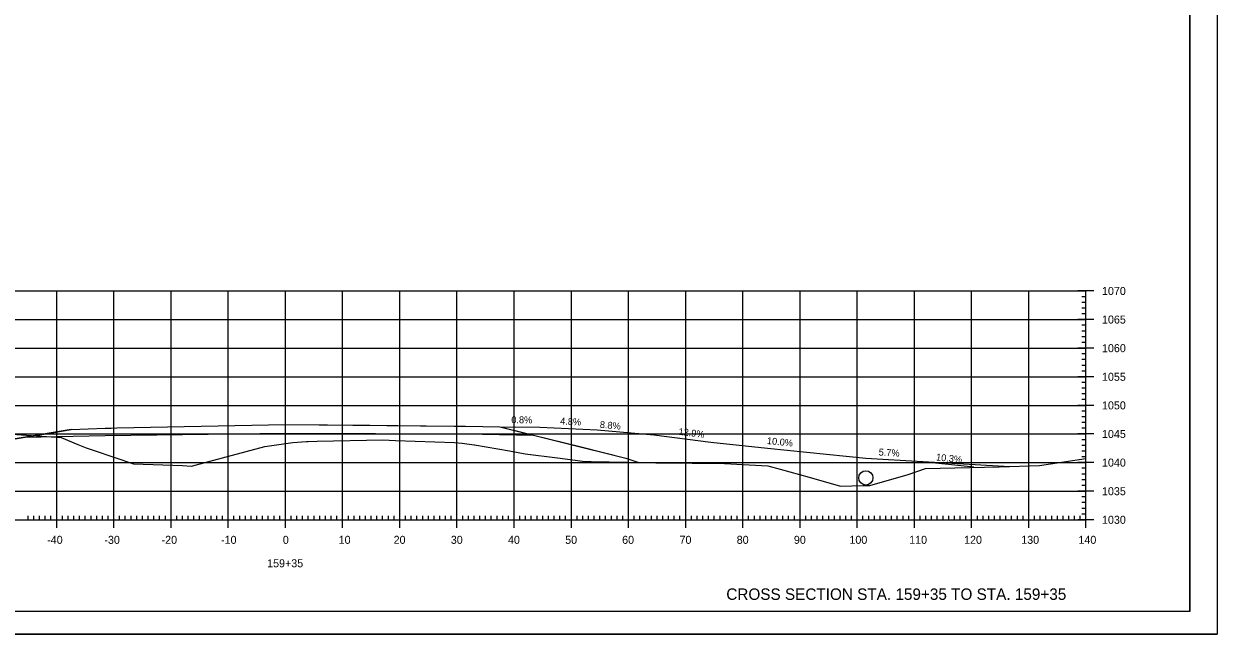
# Model space of a CAD drawing. Extents: x 1322838 to 1324533, y 339903 to 351025.
# Drawn here: x 1324107.5 to 1324316.2, y 345572 to 345678.7 of the extents above; entities that cross this region are included whole.
import ezdxf

# ---------------------------------------------------------------- set-up
doc = ezdxf.new("R2010")
doc.units = 0
for name, color, linetype in [('R_Alt Surface', 7, 'Continuous'), ('R_Axis', 7, 'Continuous'), ('R_Axis Annot', 7, 'Continuous'), ('R_Border', 7, 'Continuous'), ('R_Draft', 7, 'Continuous'), ('R_Drive', 7, 'Continuous'), ('R_Exist Surface', 7, 'Continuous'), ('R_Fin Surface', 7, 'Continuous'), ('R_Grid', 7, 'Continuous'), ('R_MOT', 7, 'Continuous'), ('R_No Plot', 7, 'Continuous'), ('R_Water', 7, 'Continuous')]:
    doc.layers.add(name, color=color, linetype=linetype)

msp = doc.modelspace()

# ---------------------------------------------------------------- linework, layer by layer
at = {"layer": 'R_Alt Surface'}
for points in [[(1324115.74, 345607.74), (1324093.74, 345604.08), (1324073.62, 345610.78)], [(1324107.75, 345606.41), (1324121.74, 345606.69), (1324153.24, 345607.11), (1324184.74, 345607.01), (1324196.63, 345606.78)], [(1324190.74, 345608.25), (1324212.74, 345602.75), (1324214.87, 345602.04)]]:
    msp.add_lwpolyline(points, dxfattribs=at)
at = {"layer": 'R_Axis'}
for p, q in [((1324294.64, 345631.97), (1324291.84, 345631.97)), ((1324293.24, 345591.97), (1324293.24, 345631.97)), ((1324293.24, 345630.97), (1324292.54, 345630.97)), ((1324293.24, 345629.97), (1324292.54, 345629.97)), ((1324293.24, 345628.97), (1324292.54, 345628.97)), ((1324293.24, 345627.97), (1324292.54, 345627.97)), ((1324294.64, 345626.97), (1324291.84, 345626.97)), ((1324293.24, 345625.97), (1324292.54, 345625.97)), ((1324293.24, 345624.97), (1324292.54, 345624.97)), ((1324293.24, 345623.97), (1324292.54, 345623.97)), ((1324293.24, 345622.97), (1324292.54, 345622.97)), ((1324294.64, 345621.97), (1324291.84, 345621.97)), ((1324293.24, 345620.97), (1324292.54, 345620.97)), ((1324293.24, 345619.97), (1324292.54, 345619.97)), ((1324293.24, 345618.97), (1324292.54, 345618.97)), ((1324294.64, 345616.97), (1324291.84, 345616.97)), ((1324293.24, 345617.97), (1324292.54, 345617.97)), ((1324293.24, 345615.97), (1324292.54, 345615.97)), ((1324293.24, 345614.97), (1324292.54, 345614.97)), ((1324293.24, 345613.97), (1324292.54, 345613.97)), ((1324293.24, 345612.97), (1324292.54, 345612.97)), ((1324294.64, 345611.97), (1324291.84, 345611.97)), ((1324293.24, 345610.97), (1324292.54, 345610.97)), ((1324293.24, 345609.97), (1324292.54, 345609.97)), ((1324293.24, 345608.97), (1324292.54, 345608.97)), ((1324294.64, 345606.97), (1324291.84, 345606.97)), ((1324293.24, 345607.97), (1324292.54, 345607.97)), ((1324293.24, 345605.97), (1324292.54, 345605.97)), ((1324293.24, 345604.97), (1324292.54, 345604.97)), ((1324293.24, 345603.97), (1324292.54, 345603.97)), ((1324293.24, 345602.97), (1324292.54, 345602.97)), ((1324294.64, 345601.97), (1324291.84, 345601.97)), ((1324293.24, 345600.97), (1324292.54, 345600.97)), ((1324293.24, 345599.97), (1324292.54, 345599.97)), ((1324293.24, 345598.97), (1324292.54, 345598.97)), ((1324293.24, 345597.97), (1324292.54, 345597.97)), ((1324294.64, 345596.97), (1324291.84, 345596.97)), ((1324293.24, 345595.97), (1324292.54, 345595.97)), ((1324293.24, 345594.97), (1324292.54, 345594.97)), ((1324293.24, 345593.97), (1324292.54, 345593.97)), ((1324013.24, 345591.97), (1324293.24, 345591.97)), ((1324108.24, 345591.97), (1324108.24, 345592.67)), ((1324109.24, 345591.97), (1324109.24, 345592.67)), ((1324110.24, 345591.97), (1324110.24, 345592.67)), ((1324111.24, 345591.97), (1324111.24, 345592.67)), ((1324112.24, 345591.97), (1324112.24, 345592.67)), ((1324113.24, 345590.57), (1324113.24, 345593.37)), ((1324114.24, 345591.97), (1324114.24, 345592.67)), ((1324115.24, 345591.97), (1324115.24, 345592.67)), ((1324116.24, 345591.97), (1324116.24, 345592.67)), ((1324117.24, 345591.97), (1324117.24, 345592.67)), ((1324118.24, 345591.97), (1324118.24, 345592.67)), ((1324119.24, 345591.97), (1324119.24, 345592.67)), ((1324120.24, 345591.97), (1324120.24, 345592.67)), ((1324121.24, 345591.97), (1324121.24, 345592.67)), ((1324122.24, 345591.97), (1324122.24, 345592.67)), ((1324123.24, 345590.57), (1324123.24, 345593.37)), ((1324124.24, 345591.97), (1324124.24, 345592.67)), ((1324125.24, 345591.97), (1324125.24, 345592.67)), ((1324126.24, 345591.97), (1324126.24, 345592.67)), ((1324127.24, 345591.97), (1324127.24, 345592.67)), ((1324128.24, 345591.97), (1324128.24, 345592.67)), ((1324129.24, 345591.97), (1324129.24, 345592.67)), ((1324130.24, 345591.97), (1324130.24, 345592.67)), ((1324131.24, 345591.97), (1324131.24, 345592.67)), ((1324132.24, 345591.97), (1324132.24, 345592.67)), ((1324133.24, 345590.57), (1324133.24, 345593.37)), ((1324134.24, 345591.97), (1324134.24, 345592.67)), ((1324135.24, 345591.97), (1324135.24, 345592.67)), ((1324136.24, 345591.97), (1324136.24, 345592.67)), ((1324137.24, 345591.97), (1324137.24, 345592.67)), ((1324138.24, 345591.97), (1324138.24, 345592.67)), ((1324139.24, 345591.97), (1324139.24, 345592.67)), ((1324140.24, 345591.97), (1324140.24, 345592.67)), ((1324141.24, 345591.97), (1324141.24, 345592.67)), ((1324142.24, 345591.97), (1324142.24, 345592.67)), ((1324143.24, 345590.57), (1324143.24, 345593.37)), ((1324144.24, 345591.97), (1324144.24, 345592.67)), ((1324145.24, 345591.97), (1324145.24, 345592.67)), ((1324146.24, 345591.97), (1324146.24, 345592.67)), ((1324147.24, 345591.97), (1324147.24, 345592.67)), ((1324148.24, 345591.97), (1324148.24, 345592.67)), ((1324149.24, 345591.97), (1324149.24, 345592.67)), ((1324150.24, 345591.97), (1324150.24, 345592.67)), ((1324151.24, 345591.97), (1324151.24, 345592.67)), ((1324152.24, 345591.97), (1324152.24, 345592.67)), ((1324153.24, 345590.57), (1324153.24, 345593.37)), ((1324154.24, 345591.97), (1324154.24, 345592.67)), ((1324155.24, 345591.97), (1324155.24, 345592.67)), ((1324156.24, 345591.97), (1324156.24, 345592.67)), ((1324157.24, 345591.97), (1324157.24, 345592.67)), ((1324158.24, 345591.97), (1324158.24, 345592.67)), ((1324159.24, 345591.97), (1324159.24, 345592.67)), ((1324160.24, 345591.97), (1324160.24, 345592.67)), ((1324161.24, 345591.97), (1324161.24, 345592.67)), ((1324162.24, 345591.97), (1324162.24, 345592.67)), ((1324163.24, 345590.57), (1324163.24, 345593.37)), ((1324164.24, 345591.97), (1324164.24, 345592.67)), ((1324165.24, 345591.97), (1324165.24, 345592.67)), ((1324166.24, 345591.97), (1324166.24, 345592.67)), ((1324167.24, 345591.97), (1324167.24, 345592.67)), ((1324168.24, 345591.97), (1324168.24, 345592.67)), ((1324169.24, 345591.97), (1324169.24, 345592.67)), ((1324170.24, 345591.97), (1324170.24, 345592.67)), ((1324171.24, 345591.97), (1324171.24, 345592.67)), ((1324172.24, 345591.97), (1324172.24, 345592.67)), ((1324173.24, 345590.57), (1324173.24, 345593.37)), ((1324174.24, 345591.97), (1324174.24, 345592.67)), ((1324175.24, 345591.97), (1324175.24, 345592.67)), ((1324176.24, 345591.97), (1324176.24, 345592.67)), ((1324177.24, 345591.97), (1324177.24, 345592.67)), ((1324178.24, 345591.97), (1324178.24, 345592.67)), ((1324179.24, 345591.97), (1324179.24, 345592.67)), ((1324180.24, 345591.97), (1324180.24, 345592.67)), ((1324181.24, 345591.97), (1324181.24, 345592.67)), ((1324182.24, 345591.97), (1324182.24, 345592.67)), ((1324183.24, 345590.57), (1324183.24, 345593.37)), ((1324184.24, 345591.97), (1324184.24, 345592.67)), ((1324185.24, 345591.97), (1324185.24, 345592.67)), ((1324186.24, 345591.97), (1324186.24, 345592.67)), ((1324187.24, 345591.97), (1324187.24, 345592.67)), ((1324188.24, 345591.97), (1324188.24, 345592.67)), ((1324189.24, 345591.97), (1324189.24, 345592.67)), ((1324190.24, 345591.97), (1324190.24, 345592.67)), ((1324191.24, 345591.97), (1324191.24, 345592.67)), ((1324192.24, 345591.97), (1324192.24, 345592.67)), ((1324193.24, 345590.57), (1324193.24, 345593.37)), ((1324194.24, 345591.97), (1324194.24, 345592.67)), ((1324195.24, 345591.97), (1324195.24, 345592.67)), ((1324196.24, 345591.97), (1324196.24, 345592.67)), ((1324197.24, 345591.97), (1324197.24, 345592.67)), ((1324198.24, 345591.97), (1324198.24, 345592.67)), ((1324199.24, 345591.97), (1324199.24, 345592.67)), ((1324200.24, 345591.97), (1324200.24, 345592.67)), ((1324201.24, 345591.97), (1324201.24, 345592.67)), ((1324202.24, 345591.97), (1324202.24, 345592.67)), ((1324203.24, 345590.57), (1324203.24, 345593.37)), ((1324204.24, 345591.97), (1324204.24, 345592.67)), ((1324205.24, 345591.97), (1324205.24, 345592.67)), ((1324206.24, 345591.97), (1324206.24, 345592.67)), ((1324207.24, 345591.97), (1324207.24, 345592.67)), ((1324208.24, 345591.97), (1324208.24, 345592.67)), ((1324209.24, 345591.97), (1324209.24, 345592.67)), ((1324210.24, 345591.97), (1324210.24, 345592.67)), ((1324211.24, 345591.97), (1324211.24, 345592.67)), ((1324212.24, 345591.97), (1324212.24, 345592.67)), ((1324213.24, 345590.57), (1324213.24, 345593.37)), ((1324214.24, 345591.97), (1324214.24, 345592.67)), ((1324215.24, 345591.97), (1324215.24, 345592.67)), ((1324216.24, 345591.97), (1324216.24, 345592.67)), ((1324217.24, 345591.97), (1324217.24, 345592.67)), ((1324218.24, 345591.97), (1324218.24, 345592.67)), ((1324219.24, 345591.97), (1324219.24, 345592.67)), ((1324220.24, 345591.97), (1324220.24, 345592.67)), ((1324221.24, 345591.97), (1324221.24, 345592.67)), ((1324222.24, 345591.97), (1324222.24, 345592.67)), ((1324223.24, 345590.57), (1324223.24, 345593.37)), ((1324224.24, 345591.97), (1324224.24, 345592.67)), ((1324225.24, 345591.97), (1324225.24, 345592.67)), ((1324226.24, 345591.97), (1324226.24, 345592.67)), ((1324227.24, 345591.97), (1324227.24, 345592.67)), ((1324228.24, 345591.97), (1324228.24, 345592.67)), ((1324229.24, 345591.97), (1324229.24, 345592.67)), ((1324230.24, 345591.97), (1324230.24, 345592.67)), ((1324231.24, 345591.97), (1324231.24, 345592.67)), ((1324232.24, 345591.97), (1324232.24, 345592.67)), ((1324233.24, 345590.57), (1324233.24, 345593.37)), ((1324234.24, 345591.97), (1324234.24, 345592.67)), ((1324235.24, 345591.97), (1324235.24, 345592.67)), ((1324236.24, 345591.97), (1324236.24, 345592.67)), ((1324237.24, 345591.97), (1324237.24, 345592.67)), ((1324238.24, 345591.97), (1324238.24, 345592.67)), ((1324239.24, 345591.97), (1324239.24, 345592.67)), ((1324240.24, 345591.97), (1324240.24, 345592.67)), ((1324241.24, 345591.97), (1324241.24, 345592.67)), ((1324242.24, 345591.97), (1324242.24, 345592.67)), ((1324243.24, 345590.57), (1324243.24, 345593.37)), ((1324244.24, 345591.97), (1324244.24, 345592.67)), ((1324245.24, 345591.97), (1324245.24, 345592.67)), ((1324246.24, 345591.97), (1324246.24, 345592.67)), ((1324247.24, 345591.97), (1324247.24, 345592.67)), ((1324248.24, 345591.97), (1324248.24, 345592.67)), ((1324249.24, 345591.97), (1324249.24, 345592.67)), ((1324250.24, 345591.97), (1324250.24, 345592.67)), ((1324251.24, 345591.97), (1324251.24, 345592.67)), ((1324252.24, 345591.97), (1324252.24, 345592.67)), ((1324253.24, 345590.57), (1324253.24, 345593.37)), ((1324254.24, 345591.97), (1324254.24, 345592.67)), ((1324255.24, 345591.97), (1324255.24, 345592.67)), ((1324256.24, 345591.97), (1324256.24, 345592.67)), ((1324257.24, 345591.97), (1324257.24, 345592.67)), ((1324258.24, 345591.97), (1324258.24, 345592.67)), ((1324259.24, 345591.97), (1324259.24, 345592.67)), ((1324260.24, 345591.97), (1324260.24, 345592.67)), ((1324261.24, 345591.97), (1324261.24, 345592.67)), ((1324262.24, 345591.97), (1324262.24, 345592.67)), ((1324263.24, 345590.57), (1324263.24, 345593.37)), ((1324264.24, 345591.97), (1324264.24, 345592.67)), ((1324265.24, 345591.97), (1324265.24, 345592.67)), ((1324266.24, 345591.97), (1324266.24, 345592.67)), ((1324267.24, 345591.97), (1324267.24, 345592.67)), ((1324268.24, 345591.97), (1324268.24, 345592.67)), ((1324269.24, 345591.97), (1324269.24, 345592.67)), ((1324270.24, 345591.97), (1324270.24, 345592.67)), ((1324271.24, 345591.97), (1324271.24, 345592.67)), ((1324272.24, 345591.97), (1324272.24, 345592.67)), ((1324273.24, 345590.57), (1324273.24, 345593.37)), ((1324274.24, 345591.97), (1324274.24, 345592.67)), ((1324275.24, 345591.97), (1324275.24, 345592.67)), ((1324276.24, 345591.97), (1324276.24, 345592.67)), ((1324277.24, 345591.97), (1324277.24, 345592.67)), ((1324278.24, 345591.97), (1324278.24, 345592.67)), ((1324279.24, 345591.97), (1324279.24, 345592.67)), ((1324280.24, 345591.97), (1324280.24, 345592.67)), ((1324281.24, 345591.97), (1324281.24, 345592.67)), ((1324282.24, 345591.97), (1324282.24, 345592.67)), ((1324283.24, 345590.57), (1324283.24, 345593.37)), ((1324284.24, 345591.97), (1324284.24, 345592.67)), ((1324285.24, 345591.97), (1324285.24, 345592.67)), ((1324286.24, 345591.97), (1324286.24, 345592.67)), ((1324287.24, 345591.97), (1324287.24, 345592.67)), ((1324288.24, 345591.97), (1324288.24, 345592.67)), ((1324289.24, 345591.97), (1324289.24, 345592.67)), ((1324290.24, 345591.97), (1324290.24, 345592.67)), ((1324291.24, 345591.97), (1324291.24, 345592.67)), ((1324294.64, 345591.97), (1324291.84, 345591.97)), ((1324292.24, 345591.97), (1324292.24, 345592.67)), ((1324293.24, 345592.97), (1324292.54, 345592.97)), ((1324293.24, 345590.57), (1324293.24, 345593.37))]:
    msp.add_line(p, q, dxfattribs=at)
at = {"layer": 'R_Border'}
for q in [(1324311.42, 345781.43), (1323995.24, 345575.97)]:
    msp.add_line((1324311.42, 345575.97), q, dxfattribs=at)
at = {"layer": 'R_Drive'}
for p, q in [((1324217.69, 345606.83), (1324227.61, 345605.55)), ((1324227.61, 345605.55), (1324237.56, 345604.52))]:
    msp.add_line(p, q, dxfattribs=at)
for points in [[(1324190.74, 345608.25), (1324197.74, 345608.19), (1324207.73, 345607.71), (1324217.69, 345606.83)], [(1324237.56, 345604.52), (1324254.75, 345602.74), (1324264.73, 345602.17), (1324273.62, 345601.25)]]:
    msp.add_lwpolyline(points, dxfattribs=at)
at = {"layer": 'R_Exist Surface'}
msp.add_lwpolyline([(1324094.94, 345607.62), (1324114, 345606.36), (1324116.95, 345605.15), (1324118.37, 345604.57), (1324119.78, 345604.07), (1324126.67, 345601.78), (1324135.24, 345601.45), (1324136.82, 345601.36), (1324138.98, 345601.93), (1324149.63, 345604.77), (1324153.73, 345605.36), (1324154.52, 345605.47), (1324156.9, 345605.65), (1324157.2, 345605.68), (1324158.79, 345605.71), (1324170.26, 345605.93), (1324172.47, 345605.85), (1324182.78, 345605.49), (1324184.12, 345605.34), (1324186.27, 345605.09), (1324186.29, 345605.09), (1324192.42, 345604), (1324195.14, 345603.53), (1324200.83, 345602.83), (1324205.63, 345602.15), (1324206.69, 345602.15), (1324216.22, 345601.97), (1324217.99, 345601.93), (1324218.63, 345601.92), (1324230.02, 345601.81), (1324237.6, 345601.43), (1324239.76, 345600.83), (1324244.82, 345599.42), (1324250.33, 345597.87), (1324254.3, 345597.96), (1324255.46, 345597.95), (1324262.13, 345599.88), (1324265.2, 345600.91), (1324278.05, 345601.25), (1324285.13, 345601.44), (1324293.24, 345602.68)], dxfattribs=at)
at = {"layer": 'R_Fin Surface'}
for points in [[(1324100.75, 345605.24), (1324107.75, 345606.41), (1324111.75, 345607.08), (1324115.74, 345607.74), (1324118.74, 345607.86), (1324121.74, 345607.98), (1324122.74, 345608), (1324123.74, 345608.02), (1324138.49, 345608.32), (1324153.24, 345608.61), (1324167.99, 345608.49), (1324182.74, 345608.33), (1324183.74, 345608.32), (1324184.74, 345608.31), (1324187.74, 345608.27), (1324190.74, 345608.25), (1324193.67, 345607.52), (1324196.63, 345606.78), (1324204.7, 345604.76), (1324212.74, 345602.75), (1324213.62, 345602.45), (1324214.87, 345602.04)], [(1324115.74, 345607.74), (1324121.74, 345607.98), (1324123.74, 345608.02), (1324153.24, 345608.61), (1324182.74, 345608.33), (1324184.74, 345608.31), (1324190.74, 345608.25)]]:
    msp.add_lwpolyline(points, dxfattribs=at)
at = {"layer": 'R_Grid'}
for p, q in [((1324013.24, 345631.97), (1324293.24, 345631.97)), ((1324113.24, 345591.97), (1324113.24, 345631.97)), ((1324123.24, 345591.97), (1324123.24, 345631.97)), ((1324133.24, 345591.97), (1324133.24, 345631.97)), ((1324143.24, 345591.97), (1324143.24, 345631.97)), ((1324153.24, 345591.97), (1324153.24, 345631.97)), ((1324163.24, 345591.97), (1324163.24, 345631.97)), ((1324173.24, 345591.97), (1324173.24, 345631.97)), ((1324183.24, 345591.97), (1324183.24, 345631.97)), ((1324193.24, 345591.97), (1324193.24, 345631.97)), ((1324203.24, 345591.97), (1324203.24, 345631.97)), ((1324213.24, 345591.97), (1324213.24, 345631.97)), ((1324223.24, 345591.97), (1324223.24, 345631.97)), ((1324233.24, 345591.97), (1324233.24, 345631.97)), ((1324243.24, 345591.97), (1324243.24, 345631.97)), ((1324253.24, 345591.97), (1324253.24, 345631.97)), ((1324263.24, 345591.97), (1324263.24, 345631.97)), ((1324273.24, 345591.97), (1324273.24, 345631.97)), ((1324283.24, 345591.97), (1324283.24, 345631.97)), ((1324293.24, 345591.97), (1324293.24, 345631.97)), ((1324013.24, 345626.97), (1324293.24, 345626.97)), ((1324013.24, 345621.97), (1324293.24, 345621.97)), ((1324013.24, 345616.97), (1324293.24, 345616.97)), ((1324013.24, 345611.97), (1324293.24, 345611.97)), ((1324013.24, 345606.97), (1324293.24, 345606.97)), ((1324013.24, 345601.97), (1324293.24, 345601.97)), ((1324013.24, 345596.97), (1324293.24, 345596.97)), ((1324013.24, 345591.97), (1324293.24, 345591.97))]:
    msp.add_line(p, q, dxfattribs=at)
at = {"layer": 'R_MOT'}
msp.add_line((1324264.73, 345602.17), (1324279.95, 345601.3), dxfattribs=at)
at = {"layer": 'R_No Plot'}
msp.add_line((1323982.84, 345571.99), (1324316.17, 345571.99), dxfattribs=at)
for points in [[(1323982.83, 345785.33), (1324316.17, 345785.33), (1324316.17, 345571.99), (1323982.83, 345571.99)], [(1324229.16, 345781.43), (1324248.78, 345781.43), (1324248.78, 345771.55), (1324264.89, 345771.55), (1324288.09, 345771.55), (1324288.21, 345743.39), (1324311.42, 345743.39), (1324311.42, 345575.97), (1323995.24, 345575.97), (1323995.24, 345781.43)]]:
    msp.add_lwpolyline(points, close=True, dxfattribs=at)
at = {"layer": 'R_Water'}
msp.add_circle((1324254.74, 345599.3), 1.25, dxfattribs=at)

# ---------------------------------------------------------------- texts
at = {"layer": 'R_Axis Annot'}
for s, p in [('1070', (1324296.04, 345631.27)), ('1065', (1324296.04, 345626.27)), ('1060', (1324296.04, 345621.27)), ('1055', (1324296.04, 345616.27)), ('1050', (1324296.04, 345611.27)), ('1045', (1324296.04, 345606.27)), ('1040', (1324296.04, 345601.27)), ('1035', (1324296.04, 345596.27)), ('1030', (1324296.04, 345591.27)), ('-40', (1324111.58, 345587.77)), ('-30', (1324121.58, 345587.77)), ('-20', (1324131.58, 345587.77)), ('-10', (1324141.98, 345587.77)), ('0', (1324152.78, 345587.77)), ('10', (1324162.55, 345587.77)), ('20', (1324172.16, 345587.77)), ('30', (1324182.16, 345587.77)), ('40', (1324192.16, 345587.77)), ('50', (1324202.16, 345587.77)), ('60', (1324212.12, 345587.77)), ('70', (1324222.16, 345587.77)), ('80', (1324232.16, 345587.77)), ('90', (1324242.16, 345587.77)), ('100', (1324251.87, 345587.77)), ('110', (1324262.32, 345587.77)), ('120', (1324271.92, 345587.77)), ('130', (1324281.92, 345587.77)), ('140', (1324291.92, 345587.77)), ('159+35', (1324150.04, 345583.67))]:
    msp.add_text(s, height=1.4, dxfattribs=at).set_placement(p)
at = {"layer": 'R_Draft'}
msp.add_text('CROSS SECTION STA. 159+35 TO STA. 159+35', height=2, dxfattribs=at).set_placement((1324230.34, 345577.97))
at = {"layer": 'R_Drive'}
for s, rotation, p in [('0.8%', 359.5241, (1324192.74, 345608.86)), ('4.8%', 357.2341, (1324201.26, 345608.63)), ('8.8%', 354.9441, (1324208.18, 345608.05)), ('12.9%', 352.6541, (1324221.93, 345606.85)), ('10.0%', 354.0941, (1324237.4, 345605.23)), ('5.7%', 356.7341, (1324256.96, 345603.22)), ('10.3%', 354.0941, (1324266.98, 345602.36))]:
    msp.add_text(s, height=1.2, rotation=rotation, dxfattribs=at).set_placement(p)

doc.saveas('drawing.dxf')
